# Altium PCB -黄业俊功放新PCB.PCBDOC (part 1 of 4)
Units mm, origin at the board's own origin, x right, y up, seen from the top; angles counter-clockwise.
Board outline 130 x 100.6 mm, 2 copper layers (Top Layer, Bottom Layer); 47 components, 24 nets, 117 pads, 4 vias.
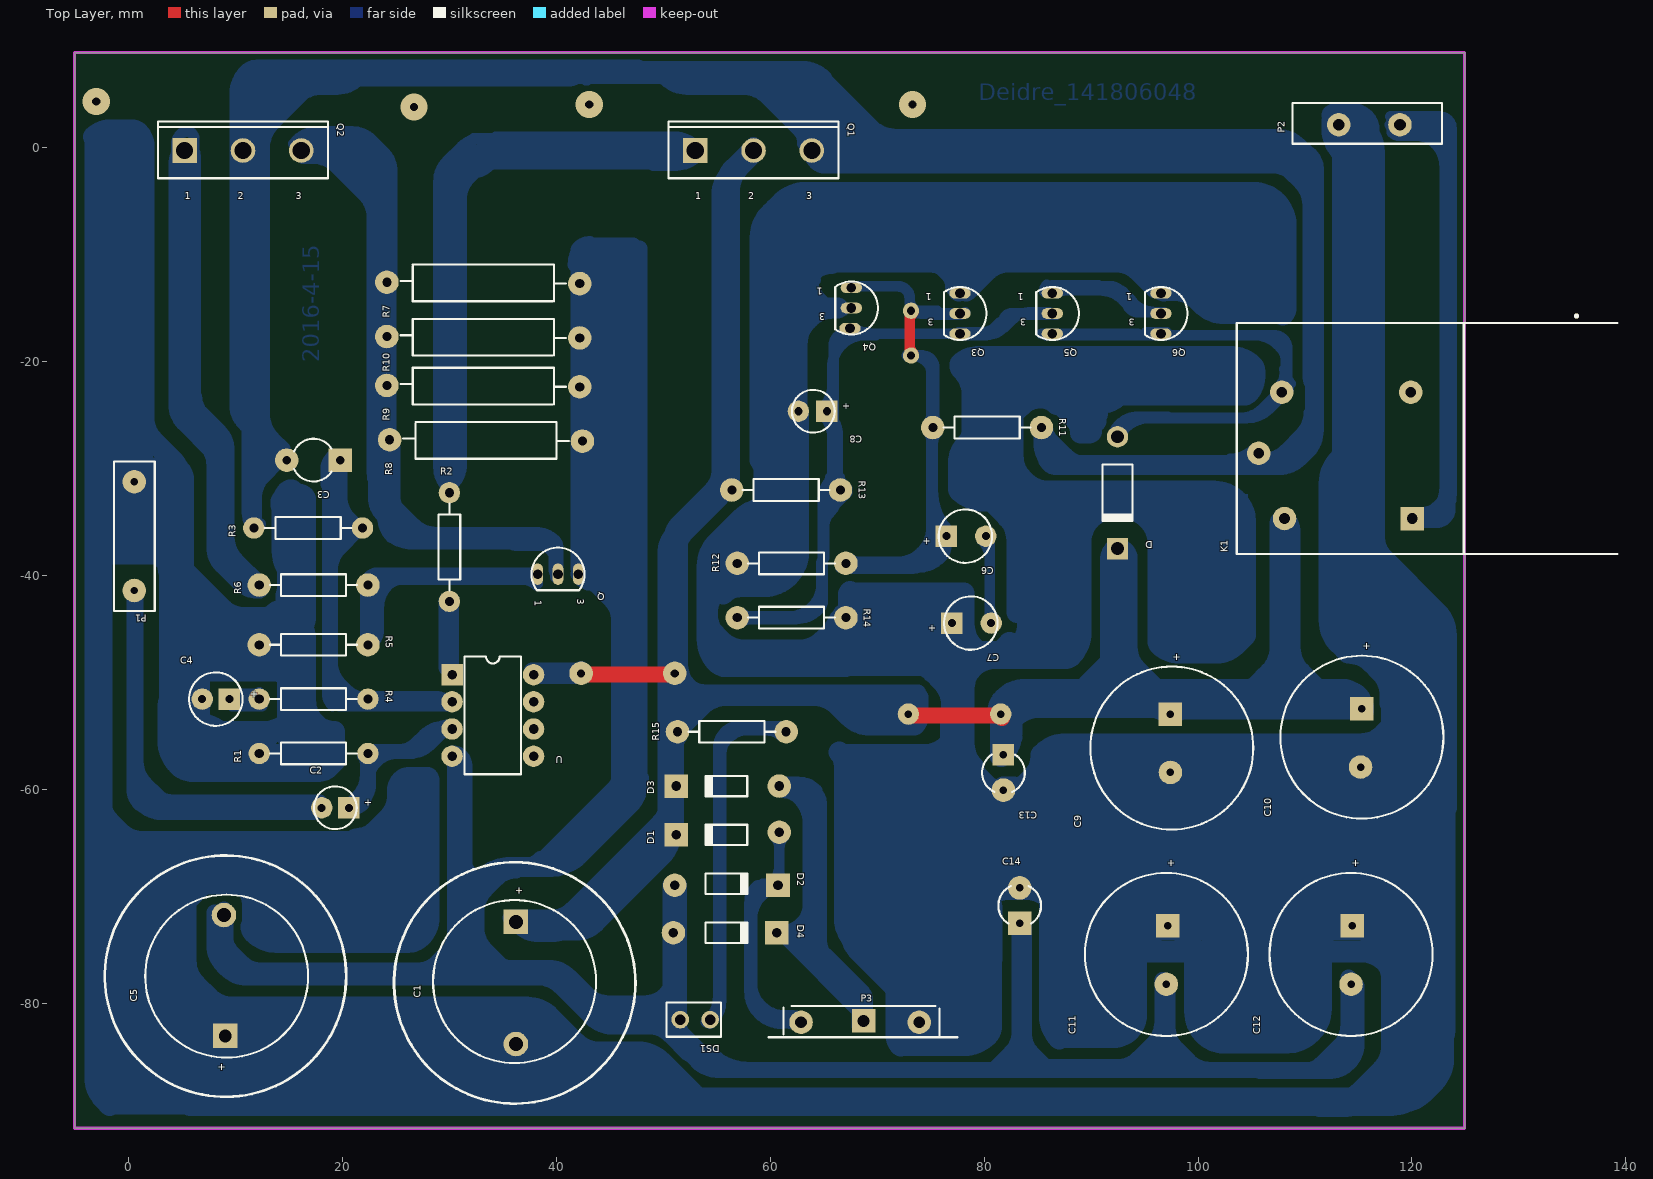
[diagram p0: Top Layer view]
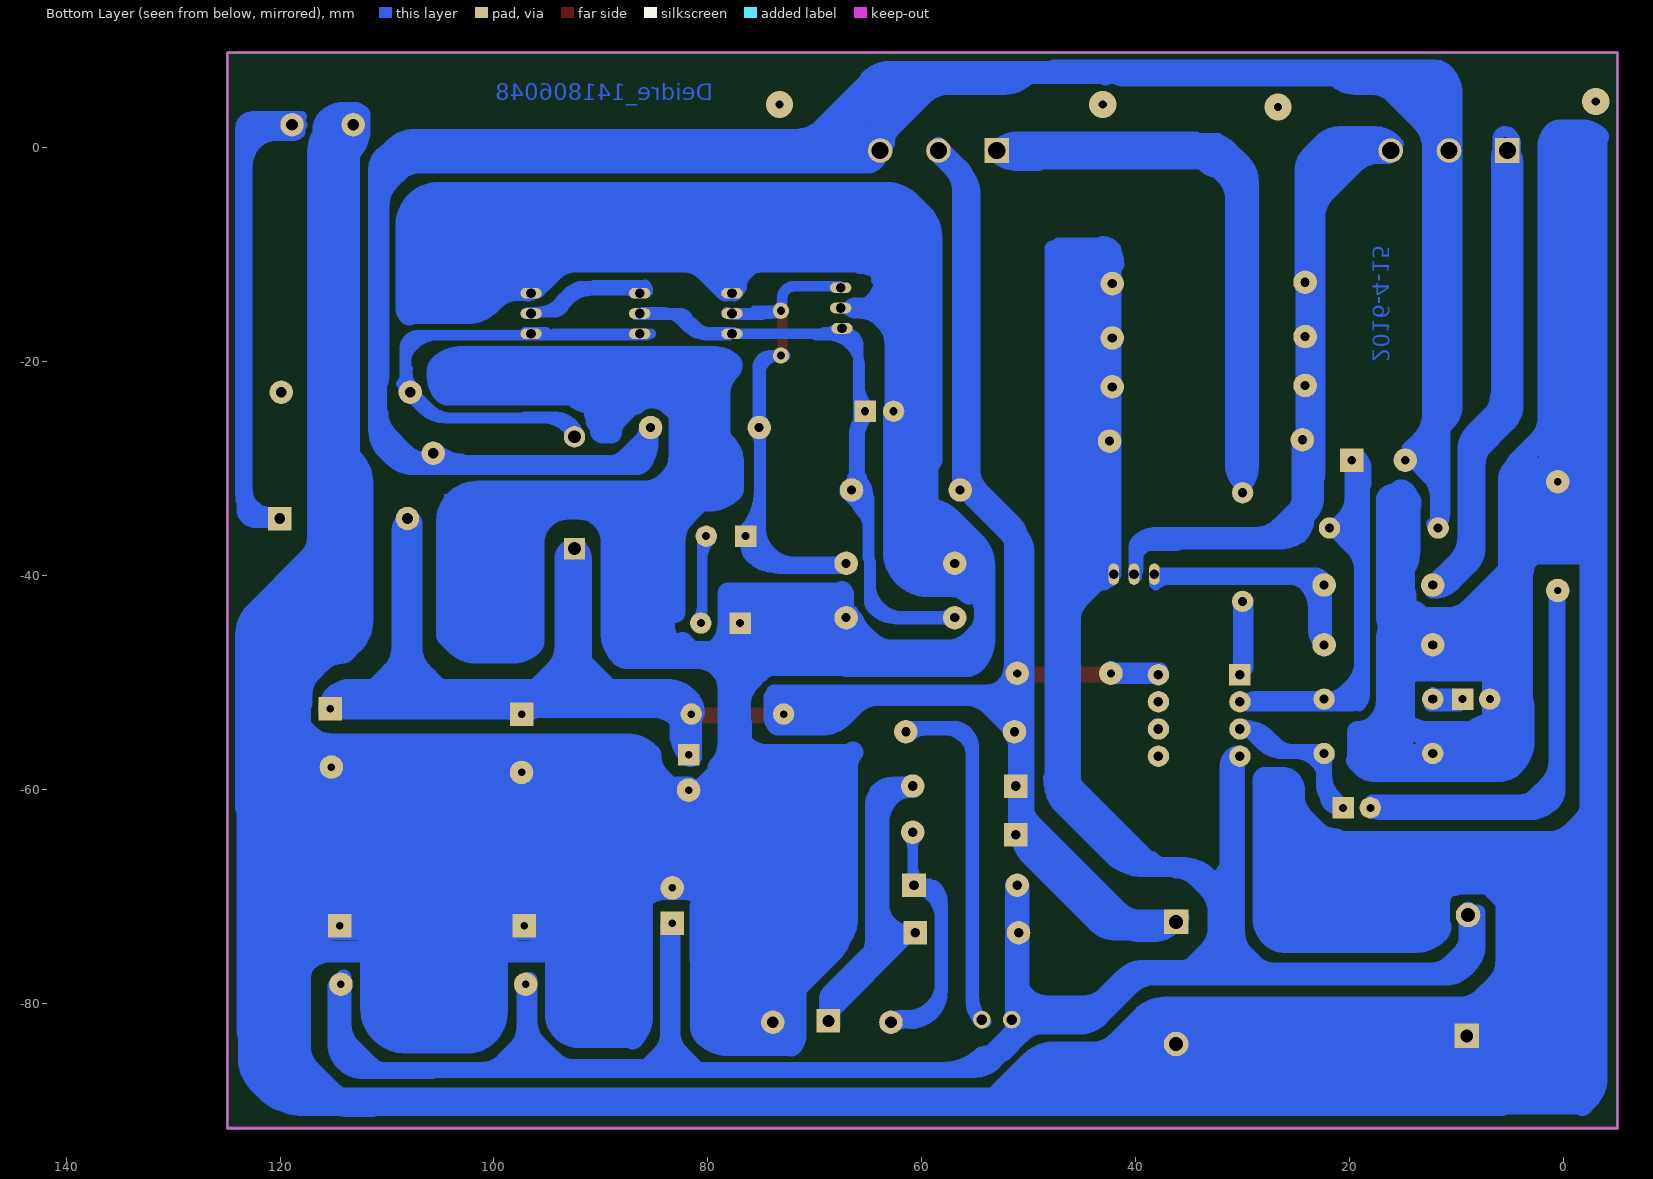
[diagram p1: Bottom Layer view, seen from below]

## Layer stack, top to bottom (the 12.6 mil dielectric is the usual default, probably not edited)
Top Layer: signal copper 0.0356
Dielectric: dielectric 0.32, FR-4, Dk 4.8
Bottom Layer: signal copper 0.0356

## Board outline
-5.08,-91.694 124.92,-91.694 124.92,8.906 -5.08,8.906

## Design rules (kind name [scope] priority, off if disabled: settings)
Clearance [All] p1: gap=0.5
ComponentClearance [All] p1: gap=0.254 collisioncheckmode=0
PolygonConnect [All] p1: connectstyle=Relief reliefconductorwidth=0.254 reliefentries=4 polygonreliefangle="90 Angle"
RoutingVias [All] p1: holewidth=0.6 width=1 viastyle="Through Hole" minholewidth=0.711 minwidth=1.27 maxholewidth=0.711 maxwidth=1.27
SolderMaskExpansion [All] p1: expansion=0.102
TestPointUsage [All] p1: valid=0 allowmultiple=FALSE
Testpoint [All] p1: side=15 testpointundercomponent=TRUE minsize=1.016 maxsize=2.54 preferedsize=1.524 minholesize=0 maxholesize=1.016 preferedholesize=0.813 testpointgrid=0.025 style=1023 order=1234567890
Width Width_3 [InNet('GND')] p1: maxlimit=14 minlimit=0.254 preferedwidth=2
Width Width_2 [InNet('+12V')] p2: maxlimit=5 minlimit=0.254 preferedwidth=1.5
Width Width_1 [InNet('-12V')] p3: maxlimit=4 minlimit=0.254 preferedwidth=1.5
Width [All] p4: maxlimit=2 minlimit=0.2 preferedwidth=1
17 further rules are at their usual default settings.

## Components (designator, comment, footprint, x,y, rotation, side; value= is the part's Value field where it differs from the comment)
C1 "Cap Pol1" RB7.6-15#1 36.068,-77.978 r90 top
C2 "Cap Pol1" CAPPR1.5-4x5#1 19.304,-61.722 r180 top
C3 "Cap" CAPR5-4X5#1 17.272,-29.21 r180 top
C4 "Cap Pol1" CAPPR2-5x6.8#1 8.128,-51.562 r180 top
C5 "Cap Pol1" RB7.6-15#2 9.144,-77.47 r270 top
C6 "Cap Pol1" CAPPR2-5x6.8#2 78.232,-36.322 r0 top (schematic designator C7)
C7 "Cap Pol1" CAPPR2-5x6.8#2 78.74,-44.45 r0 top
C8 "Cap Pol1" CAPPR1.5-4x5#2 64.008,-24.638 r180 top
C9 "Cap Pol1" RB7.6-15#3 97.536,-56.134 r90 top
C10 "Cap Pol1" RB7.6-15#4 115.316,-55.118 r90 top
C11 "Cap Pol1" RB7.6-15#5 97.028,-75.438 r90 top
C12 "Cap Pol1" RB7.6-15#5 114.3,-75.438 r90 top
C13 "Cap" CAPR5-4X5#2 81.788,-58.42 r270 top
C14 "Cap" CAPR5-4X5#3 83.312,-70.866 r90 top
D "1N4001" DIO10.46-5.3x2.8 92.456,-32.258 r270 top
D1 "Diode 1N914" DIO7.1-3.9x1.9#1 55.88,-64.262 r180 top
D2 "Diode 1N914" DIO7.1-3.9x1.9#2 55.88,-68.834 r0 top
D3 "Diode 1N914" DIO7.1-3.9x1.9#3 55.88,-59.69 r180 top
D4 "Diode 1N914" DIO7.1-3.9x1.9#3 55.88,-73.406 r0 top
DS1 "LED0" CAPR2.54-5.1x3.2 52.832,-81.534 r180 top
K1 "Relay-SPDT" DIP-P5/X1.65 121.412,-27.178 r180 top
P1 "Header 2" RAD-0.4#1 0.508,-36.322 r270 top
P2 "Header 2" RAD-0.4#2 115.824,2.286 r180 top
P3 "Header 3" HDR1X3 71.12,-81.788 r180 top
Q "BC547" BCY-W3/E4#1 40.132,-39.878 r270 top
Q1 "IRFPC50" TO-247AC 58.42,-0.254 r0 top
Q2 "IRFPC50" TO-247AC 10.668,-0.254 r0 top
Q3 "9014" BCY-W3/E4#1 77.724,-15.494 r180 top
Q4 "9014" BCY-W3/E4#2 67.564,-14.986 r180 top
Q5 "8050" BCY-W3/E4#1 86.36,-15.494 r180 top
Q6 "8050" BCY-W3/E4#1 96.52,-15.494 r180 top
R1 "Res2" AXIAL-0.4#1 17.272,-56.642 r180 top
R2 "Res2" AXIAL-0.4#1 29.972,-37.338 r90 top
R3 "Res2" AXIAL-0.4#1 16.764,-35.56 r180 top
R4 "Res2" AXIAL-0.4#1 17.272,-51.562 r0 top
R5 "Res2" AXIAL-0.4#2 17.272,-46.482 r0 top
R6 "Res2" AXIAL-0.4#2 17.272,-40.894 r180 top
R7 "Res2" AXIAL-0.4#3 33.528,-12.7 r180 top
R8 "Res2" AXIAL-0.4#3 33.782,-27.432 r180 top (schematic designator R7)
R9 "Res2" AXIAL-0.4#3 33.528,-22.352 r180 top (schematic designator R7)
R10 "Res2" AXIAL-0.4#3 33.528,-17.78 r180 top (schematic designator R7)
R11 "Res2" AXIAL-0.4#2 80.264,-26.162 r0 top
R12 "Res2" AXIAL-0.4#2 61.976,-38.862 r180 top
R13 "Res2" AXIAL-0.4#2 61.468,-32.004 r0 top
R14 "Res2" AXIAL-0.4#2 61.976,-43.942 r0 top
R15 "Res2" AXIAL-0.4#2 56.388,-54.61 r180 top
U "NE5532AP" P008 34.036,-53.086 r270 top

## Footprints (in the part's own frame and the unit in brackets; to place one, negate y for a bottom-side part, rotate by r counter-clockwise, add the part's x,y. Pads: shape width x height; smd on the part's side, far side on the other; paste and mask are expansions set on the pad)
AXIAL-0.4#1 [mm] "Resistor; 2 Leads"
  round 2 hole 0.85: 1(-5.08,0) 2(5.08,0)
  silkscreen extent -4.06,-1.02 4.06,1.02
AXIAL-0.4#2 [mm] "Resistor; 2 Leads"
  round 2.2 hole 0.85: 1(-5.08,0) 2(5.08,0)
  silkscreen extent -4.06,-1.02 4.06,1.02
AXIAL-0.4#3 [mm] "Resistor; 2 Leads"
  round 2.2 hole 0.85: 1(-8.636,0) 2(9.398,-0.127)
  silkscreen extent -7.37,-1.78 8.13,1.65
BCY-W3/E4#1 [mm] "TO, Flat Index; 3 In-Line, Axial Leads; Body Dia. 4.7mm"
  oval 2x1 hole 0.9: 1(0,-1.905) 2(0,0) 3(0,1.905)
  silkscreen extent -2.48,-2.48 1.5,2.48
BCY-W3/E4#2 [mm] "TO, Flat Index; 3 In-Line, Axial Leads; Body Dia. 4.7mm"
  oval 2x1 hole 0.9: 1(0,-1.905) 2(0,0) 3(0.127,1.905)
  silkscreen extent -2.48,-2.48 1.5,2.48
CAPPR1.5-4x5#1 [mm] "Capacitor, Electrolytic, Radial; Body 4 x 5 mm (Dia.xH typ); Pin Spacing 1.5 mm (typ)"
  rect 2x2 hole 0.75: 1(-1.27,0)
  round 2 hole 0.75: 2(1.27,0)
  silkscreen extent -2,-2 2,2
CAPPR1.5-4x5#2 [mm] "Capacitor, Electrolytic, Radial; Body 4 x 5 mm (Dia.xH typ); Pin Spacing 1.5 mm (typ)"
  rect 2x2 hole 0.75: 1(-1.27,0)
  round 2 hole 0.75: 2(1.397,0)
  silkscreen extent -2,-2 2,2
CAPPR2-5x6.8#1 [mm] "Capacitor, Electrolytic, Radial; Body 5 x 6.8 mm (Dia.xH typ); Pin Spacing 2 mm (typ)"
  rect 2x2 hole 0.75: 1(-1.27,0)
  round 2 hole 0.75: 2(1.27,0)
  silkscreen extent -2.5,-2.5 2.5,2.5
CAPPR2-5x6.8#2 [mm] "Capacitor, Electrolytic, Radial; Body 5 x 6.8 mm (Dia.xH typ); Pin Spacing 2 mm (typ)"
  rect 2x2 hole 0.75: 1(-1.778,0)
  round 2 hole 0.75: 2(1.905,0)
  silkscreen extent -2.5,-2.5 2.5,2.5
CAPR2.54-5.1x3.2 [mm] "Capacitor, Ceramic, Thru-Hole, Dipped Radial; Body 5.1 x 3.2 mm (WxT) Pin Spacing 2.54 mm (typ)"
  round 1.65 hole 1: 1(-1.524,0) 2(1.27,0)
  silkscreen extent -2.55,-1.6 2.55,1.6
CAPR5-4X5#1 [mm] "Capacitor; 2 Leads"
  rect 2.2x2.2 hole 0.8: 1(-2.5,0)
  round 2.2 hole 0.8: 2(2.5,0)
  silkscreen extent -1.69,-2 1.82,2
CAPR5-4X5#2 [mm] "Capacitor; 2 Leads"
  rect 2x2 hole 0.7: 1(-1.651,0)
  round 2.2 hole 0.7: 2(1.651,0)
  silkscreen extent -1.69,-2 1.82,2
CAPR5-4X5#3 [mm] "Capacitor; 2 Leads"
  rect 2.2x2.2 hole 0.7: 1(-1.651,0)
  round 2.2 hole 0.7: 2(1.651,0)
  silkscreen extent -1.69,-2 1.82,2
DIO7.1-3.9x1.9#1 [mm] "Diode, Axial; Body 3.8 x 1.9 mm (LxDia. max), Lead Dia. 0.53 mm (max)"
  round 2.2 hole 0.9: 1(-4.953,-0.254)
  rect 2.2x2.2 hole 0.9: 2(4.699,0)
  silkscreen extent -1.95,-0.95 2.05,0.95
DIO7.1-3.9x1.9#2 [mm] "Diode, Axial; Body 3.8 x 1.9 mm (LxDia. max), Lead Dia. 0.53 mm (max)"
  round 2.2 hole 0.9: 1(-4.826,-0.127)
  rect 2.2x2.2 hole 0.9: 2(4.826,-0.127)
  silkscreen extent -1.95,-0.95 2.05,0.95
DIO7.1-3.9x1.9#3 [mm] "Diode, Axial; Body 3.8 x 1.9 mm (LxDia. max), Lead Dia. 0.53 mm (max)"
  round 2.2 hole 0.9: 1(-4.953,0)
  rect 2.2x2.2 hole 0.9: 2(4.699,0)
  silkscreen extent -1.95,-0.95 2.05,0.95
DIO10.46-5.3x2.8 [mm] "Diode, Axial; Body 5.2 x 2.7 mm (LxDia. max), Lead Dia. 0.86 mm (max)"
  round 2 hole 1.2: 1(-5.23,0)
  rect 2x2 hole 1.2: 2(5.23,0)
  silkscreen extent -2.65,-1.4 2.75,1.4
DIP-P5/X1.65 [mm] "DIP; 5 Round Pins; Row Space 15.24 mm; Pitch 2.54 mm"
  rect 2.2x2.2 hole 1: 1(1.397,7.493)
  round 2.2 hole 1: 2(1.524,-4.318) 3(15.748,1.397) 4(13.335,7.493) 5(13.589,-4.318)
  silkscreen extent -17.8,-11.57 17.8,10.81
HDR1X3 [mm] "Connector; Header; 3 Position"
  rect 2.2x2.2 hole 1.1: 1(2.413,-0.127)
  round 2.2 hole 1.1: 2(-2.794,0) 3(8.255,0)
  silkscreen extent -6.35,-1.52 11.3,1.4
P008 [mm] "DIP; 8 Leads; Row Spacing 7.62 mm; Pitch 2.54 mm"
  rect 2x2 hole 0.9: 1(-3.81,-3.81)
  round 2 hole 0.9: 2(-1.27,-3.81) 3(1.27,-3.81) 4(3.81,-3.81) 5(3.81,3.81) 6(1.27,3.81) 7(-1.27,3.81) 8(-3.81,3.81)
  silkscreen extent -5.5,-2.65 5.5,2.65
RAD-0.4#1 [mm] "Servo Motor; 2 Leads"
  round 2.2 hole 0.7: 1(-5.08,0) 2(5.08,0)
  silkscreen extent -6.98,-1.91 6.98,1.91
RAD-0.4#2 [mm] "Servo Motor; 2 Leads"
  round 2.2 hole 1.1: 1(-3.048,0.127) 2(2.667,0.127)
  silkscreen extent -6.98,-1.91 6.98,1.91
RB7.6-15#1 [mm] "Polarized Capacitor (Radial); 2 Leads"
  rect 2.3x2.3 hole 1.3: 1(5.588,-0.127)
  round 2.3 hole 1.3: 2(-5.842,-0.127)
  silkscreen extent -7.62,-7.62 7.62,7.62
RB7.6-15#2 [mm] "Polarized Capacitor (Radial); 2 Leads"
  rect 2.3x2.3 hole 1.2: 1(5.588,-0.127)
  round 2.3 hole 1.3: 2(-5.715,-0.254)
  silkscreen extent -7.62,-7.62 7.62,7.62
RB7.6-15#3 [mm] "Polarized Capacitor (Radial); 2 Leads"
  rect 2.2x2.2 hole 0.7: 1(3.175,0.127)
  round 2.2 hole 0.7: 2(-2.286,0.127)
  silkscreen extent -7.62,-7.62 7.62,7.62
RB7.6-15#4 [mm] "Polarized Capacitor (Radial); 2 Leads"
  rect 2.2x2.2 hole 0.7: 1(2.667,0)
  round 2.2 hole 0.7: 2(-2.794,0.127)
  silkscreen extent -7.62,-7.62 7.62,7.62
RB7.6-15#5 [mm] "Polarized Capacitor (Radial); 2 Leads"
  rect 2.2x2.2 hole 0.7: 1(2.667,-0.127)
  round 2.2 hole 0.7: 2(-2.794,0)
  silkscreen extent -7.62,-7.62 7.62,7.62
TO-247AC [mm] "SIP with Mounting Hole; 3 Leads; Body 20 x 15.6 x 5 mm (typ); Pitch 5.45 mm"
  rect 2.3x2.3 hole 1.6: 1(-5.45,0)
  round 2.3 hole 1.6: 2(0,0) 3(5.45,0)
  silkscreen extent -7.95,-2.6 7.95,2.7

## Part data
C1 C2 C4 C5 C6 C7 C8 C9 C10 C11 C12: "Polarized Capacitor (Radial)"
C3 C13 C14: "Capacitor"
D: library part "Diode 1N4001", "1 Amp General Purpose Rectifier"
D1 D2 D3 D4: "High Conductance Fast Diode"
DS1: "Typical INFRARED GaAs LED"
K1: "Single-Pole Dual-Throw Relay"
P1 P2: "Header, 2-Pin"
P3: "Header, 3-Pin"
Q Q3 Q4 Q5 Q6: library part 2N3904, "NPN General Purpose Amplifier"
Q1 Q2: "HEXFET Power MOSFET"
R1 R2 R3 R4 R5 R6 R7 R8 R9 R10 R11 R12 R13 R14 R15: "Resistor"
U: "Dual Low-Noise Operational Amplifier"

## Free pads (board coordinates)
  round 2.2 hole 0.762: 0(42.291,-49.149) 1(51.054,-49.149)
  round 1.524 hole 0.762: 0(73.152,-15.24) 1(73.152,-19.431)
  round 2 hole 0.7: 4(81.534,-52.959) 5(72.898,-52.959)

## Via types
v1: diameter 2.54, hole 0.762, Top Layer to Bottom Layer, 4 vias

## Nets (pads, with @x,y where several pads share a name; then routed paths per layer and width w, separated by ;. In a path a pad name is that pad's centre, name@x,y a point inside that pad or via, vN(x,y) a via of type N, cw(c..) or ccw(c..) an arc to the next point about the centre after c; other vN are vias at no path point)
+12V: C1.1 C9.1 C10.1 C13.1 D1.2 D3.2 D.2 K1.4 pad.0@42.291,-49.149 pad.1@51.054,-49.149 pad.4 pad.5 Q1.2 R13.1 R15.2 U.8 | length 1051.8
  Top Layer w1.5: pad.0@42.291,-49.276 51.054,-49.276 ccw(c51.054,-49.149) pad.1@51.181,-49.149 ; pad.5@72.898,-53.086 81.048,-53.086 cw(c81.048,-53.953) pad.4@81.661,-53.34
  Bottom Layer w1.5: C1.1@35.687,-72.009 39.562,-72.009 ccw(c39.562,-69.407) 41.402,-71.247 49.629,-63.02 ccw(c47.721,-61.112) 50.419,-61.112 50.419,-60.96 ; C1.1@36.576,-72.009 37.183,-72.616 ccw(c39.091,-70.708) 39.091,-73.406 41.808,-73.406 ccw(c41.808,-70.708) 43.716,-72.616 50.01,-66.322 ccw(c48.102,-64.414) 50.8,-64.414 50.8,-63.246 50.8,-61.341 ; U.8@37.719,-49.403 41.783,-49.403 ccw(c41.783,-49.022) pad.0@42.164,-49.022 ; U.8@37.719,-48.895 41.984,-48.895 ccw(c41.984,-48.461) pad.0@42.291,-48.768 ; D1.2@50.165,-63.754 50.165,-37.948 cw(c52.863,-37.948) 50.955,-36.04 54.963,-32.032 ccw(c53.055,-30.124) 55.753,-30.124 55.753,-24.765 ; 50.673,-40.386 50.673,-36.932 cw(c53.371,-36.932) 51.463,-35.024 54.455,-32.032 ccw(c52.547,-30.124) 55.245,-30.124 55.245,-4.293 cw(c57.943,-4.293) 56.035,-2.385 Q1.2@58.293,-0.127 ; 50.8,-61.976 cw(c50.493,-62.283) 50.927,-62.283 50.927,-62.382 cw(c48.229,-62.382) 50.137,-64.29 42.7,-71.727 cw(c40.792,-69.819) 40.792,-72.517 35.941,-72.517 cw(c35.941,-73.13) 36.375,-72.697 36.421,-72.743 ccw(c38.329,-70.835) 38.329,-73.533 39.522,-73.533 ccw(c39.522,-70.835) 41.43,-72.743 50.239,-63.934 ccw(c49.806,-63.5) 50.419,-63.5 50.419,-56.109 cw(c53.117,-56.109) 51.209,-54.201 52.832,-52.578 ; 50.8,-58.166 50.8,-38.329 ; 50.8,-39.497 50.8,-38.202 cw(c53.498,-38.202) 51.59,-36.294 55.88,-32.004 cw(c56.493,-31.391) 55.626,-31.391 55.626,-3.658 cw(c58.324,-3.658) 56.416,-1.75 Q1.2@58.42,0.254 ; 50.912,-60.89 ccw(c48.483,-59.715) D3.2@51.181,-59.715 ; D3.2@50.927,-60.604 D3.2@50.927,-59.563 ; R15.2@50.927,-54.61 50.927,-54.356 cw(c53.993,-54.356) 51.181,-53.134 cw(c53.993,-54.356) 51.308,-52.876 cw(c53.993,-54.356) 51.562,-52.488 cw(c53.993,-54.356) 51.825,-52.188 cw(c53.03,-53.393) 53.03,-51.689 54.229,-51.689 ; 50.927,-47.625 50.927,-38.202 cw(c53.625,-38.202) 51.717,-36.294 54.963,-33.048 ccw(c53.055,-31.14) 55.753,-31.14 55.753,-28.321 ; R15.2@51.061,-54.363 ccw(c49.85,-53.152) 51.562,-53.152 ; D1.2@51.181,-64.135 R15.2@51.181,-54.61 ; R15.2@51.181,-54.483 51.181,-38.608 ; R15.2@51.181,-54.229 ccw(c49.341,-52.389) 51.308,-54.093 ccw(c49.341,-52.389) R15.2@51.561,-53.747 ; 51.181,-53.458 ccw(c52.46,-53.458) R15.2@51.555,-54.363 ; R15.2@51.308,-54.483 ccw(c51.308,-54.61) R15.2@51.292,-54.484 ; 51.308,-38.227 51.308,-37.948 cw(c54.006,-37.948) 52.098,-36.04 55.09,-33.048 ccw(c53.182,-31.14) 55.88,-31.14 55.88,-27.94 ; R15.2@51.435,-55.118 cw(c52.661,-55.118) 51.794,-54.251 53.712,-52.333 cw(c55.88,-54.501) 55.88,-51.435 ; 51.435,-50.673 ccw(c52.048,-50.06) 51.562,-50.778 ccw(c52.048,-50.06) 52.048,-50.927 73.787,-50.927 ; 51.435,-47.625 51.435,-48.133 ccw(c54.501,-48.133) 51.562,-49.006 ccw(c54.501,-48.133) 52.333,-50.301 52.442,-50.41 ccw(c54.61,-48.242) 53.13,-50.927 ccw(c54.61,-48.242) 54.61,-51.308 ; pad.1@51.562,-48.412 ccw(c54.26,-48.412) 52.352,-50.32 ccw(c53.817,-48.855) 52.353,-50.321 ccw(c53.817,-48.855) 53.817,-50.927 ; 51.562,-35.814 51.562,-53.69 cw(c50.261,-53.69) R15.2@51.561,-53.747 ; 54.69,-51.435 ccw(c54.69,-51.627) 54.554,-51.491 cw(c52.386,-49.323) 52.386,-52.389 51.943,-52.389 cw(c49.341,-52.389) R15.2@51.561,-53.747 ; 55.372,-51.435 72.21,-51.435 cw(c72.21,-51.869) 72.517,-51.562 ; R13.1@56.388,-31.645 56.388,-4.064 cw(c59.454,-4.064) 57.286,-1.896 Q1.2@58.674,-0.508 ; 64.008,-51.435 cw(c64.008,-54.501) 66.176,-52.333 67.174,-53.331 ccw(c69.342,-51.163) 69.342,-54.229 ccw(c69.342,-49.56) pad.5@72.717,-52.786 ; 67.31,-52.324 ccw(c69.15,-50.484) 67.605,-52.578 ccw(c69.15,-50.484) 69.15,-53.086 71.86,-53.086 ccw(c71.86,-53.064) 71.876,-53.08 ccw(c70.358,-54.597) 70.358,-52.451 ccw(c70.358,-49.385) 72.517,-51.562 ; 67.564,-52.578 68.856,-52.578 ccw(c68.856,-51.711) 69.469,-52.324 ; 67.945,-53.594 68.221,-53.594 cw(c68.221,-54.461) 68.834,-53.848 ; 68.615,-51.435 cw(c68.615,-57.242) pad.5@72.721,-53.136 ; 69.215,-54.229 73.353,-54.229 ccw(c73.353,-53.795) 73.66,-54.102 ccw(c72.74,-53.182) 74.041,-53.182 74.041,-51.488 ; 69.228,-54.229 ccw(c69.228,-49.289) pad.5@72.721,-52.782 ; 71.501,-51.308 73.607,-51.308 ccw(c73.607,-50.874) 73.914,-51.181 cw(c73.607,-51.488) 74.041,-51.488 ; 71.829,-54.229 ccw(c71.829,-53.795) 72.136,-54.102 ccw(c70.91,-52.876) 72.644,-52.876 72.644,-51.435 72.526,-51.553 cw(c70.358,-49.385) 72.517,-51.562 ; 72.644,-51.742 ccw(c74.115,-51.742) pad.5@73.075,-52.782 ; pad.5@72.884,-52.709 ccw(c72.817,-51.488) 74.041,-51.488 ; pad.4@81.026,-52.841 cw(c83.194,-52.841) 81.661,-51.308 cw(c83.807,-53.454) 83.807,-50.419 113.634,-50.419 cw(c113.634,-51.72) 114.554,-50.8 ccw(c114.861,-51.107) 114.427,-51.107 ; C13.1@81.28,-57.023 81.28,-54.037 ; 81.28,-55.193 ccw(c83.618,-55.193) C13.1@81.965,-56.846 ; 81.28,-54.176 cw(c82.751,-54.176) pad.4@81.711,-53.136 ; 81.28,-54.066 cw(c82.498,-54.066) pad.4@81.698,-53.148 ; pad.4@81.447,-53.193 cw(c80.724,-55.144) 82.804,-55.144 ; C13.1@81.534,-57.15 ccw(c81.534,-56.843) 81.751,-57.06 81.906,-56.905 ccw(c79.738,-54.737) 82.804,-54.737 82.804,-52.832 ; C13.1@81.661,-57.15 81.661,-54.439 ccw(c79.927,-54.439) 81.153,-53.213 81.906,-52.46 cw(c84.074,-54.628) 84.074,-51.562 87.757,-51.562 ; 81.915,-55.499 cw(c84.981,-55.499) 82.813,-53.331 ; 81.915,-55.294 cw(c84.486,-55.294) 82.668,-53.476 ; 81.915,-54.786 cw(c84.486,-54.786) 82.668,-52.968 cw(c84.836,-55.136) 84.836,-52.07 90.043,-52.07 ; 82.296,-54.987 cw(c84.433,-54.987) 82.922,-53.476 cw(c85.09,-55.644) 85.09,-52.578 85.344,-52.578 ccw(c85.344,-49.512) 87.512,-51.68 87.621,-51.571 cw(c89.789,-53.739) 89.789,-50.673 114.142,-50.673 cw(c114.142,-51.974) 115.062,-51.054 cw(c113.529,-52.587) 115.697,-52.587 C10.1@115.697,-52.705 ; 83.185,-51.816 97.409,-51.816 ; 83.365,-51.816 111.252,-51.816 ccw(c111.252,-48.75) 113.42,-50.918 ; 84.836,-52.578 99.441,-52.578 ; 85.852,-51.562 112.259,-51.562 ; 88.414,-51.689 ccw(c88.414,-50.822) 89.027,-51.435 89.154,-51.435 ccw(c89.154,-50.822) 89.588,-51.255 91.685,-49.158 ccw(c89.517,-46.99) 92.583,-46.99 92.583,-45.212 92.583,-46.736 ccw(c95.649,-46.736) 93.481,-48.904 95.114,-50.537 ccw(c97.282,-48.369) 97.282,-51.435 101.473,-51.435 ccw(c101.473,-56.428) C9.1@97.675,-53.186 ; 89.535,-50.038 91.558,-48.015 ccw(c89.39,-45.847) 92.456,-45.847 D.2@92.456,-37.465 ; 91.567,-47.498 91.567,-38.564 cw(c93.301,-38.564) 92.075,-37.338 ccw(c92.382,-37.031) 92.382,-37.465 92.911,-37.465 cw(c92.911,-37.899) 93.218,-37.592 ccw(c93.525,-37.899) 93.091,-37.899 93.091,-49.171 ccw(c93.958,-49.171) 93.345,-49.784 ; 91.567,-40.238 cw(c95.206,-40.238) D.2@92.633,-37.665 ; 91.567,-38.884 cw(c92.742,-38.884) D.2@92.506,-37.733 ; D.2@92.279,-37.665 cw(c90.319,-39.625) 93.091,-39.625 ; 93.191,-51.562 cw(c93.191,-57.177) C9.1@97.162,-53.206 ; 93.98,-52.324 93.481,-51.825 cw(c95.649,-49.657) 92.583,-49.657 D.2@92.583,-37.338 ; 95.644,-52.578 cw(c95.644,-54.724) C9.1@97.162,-53.206 ; 96.093,-50.627 cw(c93.761,-52.959) C9.1@97.059,-52.959 ; 96.266,-50.8 cw(c94.332,-52.734) C9.1@97.06,-52.933 ; 96.266,-50.546 94.389,-48.669 cw(c96.297,-46.761) 93.599,-46.761 93.599,-38.49 ccw(c92.351,-38.49) 93.233,-37.607 ccw(c92.583,-38.258) D.2@92.583,-37.338 ; C9.1@96.596,-52.146 cw(c96.779,-52.329) C9.1@96.779,-52.07 ; 96.774,-51.308 93.481,-48.015 cw(c95.649,-45.847) 92.583,-45.847 D.2@92.583,-37.338 ; C9.1@97.028,-52.07 112.014,-52.07 ; C9.1@97.536,-52.705 C10.1@115.189,-52.705 ; C9.1@97.656,-52.698 cw(c99.174,-54.216) 99.174,-52.07 ; 99.174,-52.578 ccw(c99.174,-54.724) C9.1@97.656,-53.206 ; 100.4,-52.07 ccw(c100.4,-55.95) C9.1@97.656,-53.206 ; 101.013,-51.816 ccw(c101.013,-56.563) C9.1@97.656,-53.206 ; 101.627,-51.562 ccw(c101.627,-57.177) C9.1@97.656,-53.206 ; 103.632,-51.943 cw(c103.939,-51.943) 103.722,-51.726 106.925,-48.523 ccw(c104.757,-46.355) 107.823,-46.355 K1.4@107.823,-34.544 ; 103.632,-51.689 ccw(c103.632,-48.623) 105.8,-50.791 107.052,-49.539 ccw(c104.884,-47.371) 107.95,-47.371 107.95,-40.132 ; 105.918,-49.53 106.544,-48.904 ccw(c104.376,-46.736) 107.442,-46.736 107.442,-35.105 cw(c107.876,-35.105) 107.569,-34.798 cw(c108.182,-35.411) 108.182,-34.544 108.316,-34.677 cw(c107.052,-35.941) 108.839,-35.941 108.839,-46.736 ccw(c111.905,-46.736) 109.737,-48.904 110.617,-49.784 ; 107.442,-37.049 cw(c110.455,-37.049) K1.4@108.324,-34.918 ; K1.4@107.823,-34.417 107.823,-51.658 ccw(c109.124,-51.658) 108.204,-52.578 ; K1.4@107.83,-34.918 cw(c105.392,-37.356) 108.839,-37.356 ; 107.95,-45.593 107.95,-47.117 ccw(c111.016,-47.117) 108.848,-49.285 111.506,-51.943 ; 107.95,-35.823 cw(c109.229,-35.823) K1.4@108.324,-34.918 ; K1.4@107.95,-34.671 107.95,-45.847 ccw(c111.016,-45.847) 108.848,-48.015 ; K1.4@107.979,-35.007 cw(c107.647,-36.152) 108.839,-36.152 ; K1.4@108.077,-34.671 108.077,-45.974 ccw(c111.143,-45.974) 108.975,-48.142 113.157,-52.324 ; 109.855,-51.435 110.744,-51.435 ccw(c110.744,-48.369) 112.912,-50.537 ; 110.179,-50.673 cw(c110.179,-57.588) C10.1@115.069,-52.698 ; 113.665,-51.435 ccw(c113.972,-51.435) 113.755,-51.652 ; 113.858,-52.705 ccw(c113.858,-50.993) C10.1@115.069,-52.204 ; C10.1@114.427,-52.324 114.427,-51.107 ; C10.1@115.345,-52.102 cw(c115.426,-51.107) 114.427,-51.107 ; 51.181,-55.762 cw(c52.46,-55.762) R15.2@51.555,-54.857 ; 51.181,-55.762 cw(c52.46,-55.762) R15.2@51.555,-54.857 ; 51.181,-55.762 cw(c52.46,-55.762) R15.2@51.555,-54.857 ; 51.181,-55.762 cw(c52.46,-55.762) R15.2@51.555,-54.857 ; 51.181,-55.762 cw(c52.46,-55.762) R15.2@51.555,-54.857 ; R15.2@51.181,-54.61 ccw(c50.261,-53.69) R15.2@51.292,-54.484 ; R15.2@51.181,-54.61 cw(c51.308,-54.61) R15.2@51.292,-54.484 ; R15.2@51.292,-54.484 ccw(c50.261,-53.69) 51.308,-54.462 ccw(c50.261,-53.69) R15.2@51.561,-53.747 ; 95.031,-51.816 cw(c95.031,-54.829) C9.1@97.162,-52.698 ; 95.031,-51.816 cw(c95.031,-54.829) C9.1@97.162,-52.698 ; 95.031,-51.816 cw(c95.031,-54.829) C9.1@97.162,-52.698 ; 95.031,-51.816 cw(c95.031,-54.829) C9.1@97.162,-52.698 ; 95.951,-52.197 cw(c95.951,-53.909) C9.1@97.162,-52.698 ; 95.951,-52.197 cw(c95.951,-53.909) C9.1@97.162,-52.698 ; 95.951,-52.197 cw(c95.951,-53.909) C9.1@97.162,-52.698 ; C9.1@97.162,-53.206 ccw(c93.805,-56.563) 93.805,-51.816 cw(c93.805,-56.563) C9.1@97.162,-53.206 ; C9.1@97.656,-53.206 cw(c98.867,-54.417) 98.867,-52.705 ; C9.1@97.656,-52.204 ccw(c98.867,-50.993) 98.867,-52.705 ; C9.1@97.656,-52.204 ccw(c98.561,-51.299) 98.561,-52.578 ; C9.1@97.656,-52.204 ccw(c98.561,-51.299) 98.561,-52.578 ; C9.1@97.656,-52.204 ccw(c98.867,-50.993) 98.867,-52.705 ; C9.1@97.656,-52.204 ccw(c98.867,-50.993) 98.867,-52.705 ; C9.1@97.656,-52.204 ccw(c98.561,-51.299) 98.561,-52.578 ; C9.1@97.656,-52.204 ccw(c98.867,-50.993) 98.867,-52.705 ; K1.4@108.324,-34.918 ccw(c109.535,-36.129) 107.823,-36.129 cw(c109.535,-36.129) K1.4@108.324,-34.918 ; C10.1@115.189,-52.705 ccw(c115.189,-52.324) C10.1@115.57,-52.324 ; C10.1@115.189,-52.705 ccw(c115.189,-52.324) C10.1@115.57,-52.324 ; C10.1@115.189,-52.705 ccw(c115.189,-52.324) C10.1@115.57,-52.324 ; 115.189,-51.299 ccw(c116.468,-51.299) C10.1@115.563,-52.204 ; 115.189,-51.299 ccw(c116.468,-51.299) C10.1@115.563,-52.204 ; 115.189,-51.299 ccw(c116.468,-51.299) C10.1@115.563,-52.204 ; 115.189,-51.299 ccw(c116.468,-51.299) C10.1@115.563,-52.204
+18V: 
-12V: C5.2 C11.2 C12.2 C14.1 D2.1 D4.1 DS1.2 Q.3 R7.1 R8.1 R9.1 R10.1 U.4 | length 1048.9
  Bottom Layer w1.5: C5.2@8.001,-71.501 8.001,-74.574 ccw(c10.699,-74.574) 8.791,-76.482 9.116,-76.807 ccw(c11.024,-74.899) 11.024,-77.597 38.379,-77.597 cw(c38.379,-80.295) 40.287,-78.387 43.279,-81.379 ccw(c45.187,-79.471) 45.187,-82.169 48.666,-82.169 cw(c48.666,-84.867) 50.574,-82.959 52.324,-84.709 54,-84.709 ; C5.2@8.636,-71.755 8.636,-73.939 ccw(c11.334,-73.939) 9.426,-75.847 10.005,-76.426 ccw(c11.913,-74.518) 11.913,-77.216 39.014,-77.216 cw(c39.014,-79.914) 40.922,-78.006 43.66,-80.744 ccw(c45.568,-78.836) 45.568,-81.534 DS1.2@51.562,-81.534 ; C5.2@8.89,-71.247 8.89,-73.431 ccw(c11.588,-73.431) 9.68,-75.339 10.513,-76.172 ccw(c12.421,-74.264) 12.421,-76.962 18.288,-76.962 ; C5.2@9.017,-71.628 9.017,-73.812 ccw(c11.715,-73.812) 9.807,-75.72 10.259,-76.172 ccw(c12.167,-74.264) 12.167,-76.962 26.949,-76.962 ccw(c26.949,-74.264) 28.857,-76.172 29.69,-75.339 ccw(c27.782,-73.431) 30.48,-73.431 U.4@30.48,-57.404 ; 28.6,-77.216 ccw(c28.6,-74.518) 30.508,-76.426 31.341,-75.593 ccw(c29.433,-73.685) 31.369,-75.565 31.369,-57.76 ccw(c30.251,-57.76) 30.251,-56.642 U.4@30.226,-56.642 ; 31.115,-63.246 31.115,-66.065 ccw(c33.813,-66.065) 31.905,-67.973 ; 31.242,-66.294 ccw(c33.695,-66.294) 31.96,-68.028 32.639,-68.707 33.318,-68.028 cw(c35.052,-69.763) 35.052,-67.31 ; 31.369,-70.231 33.754,-67.846 cw(c35.662,-69.754) 35.662,-67.056 39.141,-67.056 ccw(c39.141,-64.358) 41.049,-66.266 46.454,-60.861 ccw(c44.546,-58.953) 47.244,-58.953 47.244,-10.149 ; 31.369,-69.85 33.246,-67.973 cw(c35.154,-69.881) 35.154,-67.183 37.617,-67.183 ccw(c37.617,-64.485) 39.525,-66.393 46.073,-59.845 ccw(c44.165,-57.937) 46.863,-57.937 46.863,-43.282 ccw(c44.165,-43.282) 46.073,-41.374 44.859,-40.16 ccw(c42.951,-42.068) 42.951,-39.37 Q.3@42.037,-39.37 ; 31.623,-70.104 31.623,-73.685 ccw(c34.321,-73.685) 32.413,-75.593 33.655,-76.835 ; 32.385,-74.422 33.881,-75.918 ccw(c35.789,-74.01) 35.789,-76.708 39.268,-76.708 cw(c39.268,-79.406) 41.176,-77.498 42.898,-79.22 ccw(c44.806,-77.312) 44.806,-80.01 48.285,-80.01 ccw(c48.285,-77.312) 50.193,-79.22 50.388,-79.025 ccw(c49.087,-77.724) 50.927,-77.724 ; 35.535,-67.437 ccw(c35.535,-70.135) 33.627,-68.227 32.751,-69.103 ; 35.56,-67.437 39.522,-67.437 ccw(c39.522,-64.739) 40.34,-67.31 ccw(c39.522,-64.739) 40.834,-67.097 ccw(c40.157,-64.485) 42.065,-66.393 46.962,-61.496 ccw(c45.054,-59.588) 47.698,-60.125 47.752,-60.071 cw(c48.059,-59.764) 47.716,-60.03 ; 35.56,-67.31 36.601,-67.31 ccw(c36.601,-64.612) 38.509,-66.52 ; 35.56,-67.183 ccw(c35.56,-69.636) 33.826,-67.901 33.175,-68.552 ccw(c35.083,-70.46) 32.751,-69.103 ; 35.814,-67.31 36.855,-67.31 ccw(c36.855,-64.612) 38.763,-66.52 45.311,-59.972 ccw(c43.403,-58.064) 46.101,-58.064 46.101,-43.663 ccw(c43.403,-43.663) 45.311,-41.755 44.732,-41.176 ccw(c42.824,-43.084) 42.824,-40.386 Q.3@42.418,-40.386 ; 36.195,-67.564 ccw(c36.195,-70.017) 34.461,-68.282 33.302,-69.441 ccw(c35.21,-71.349) 32.512,-71.349 32.512,-73.05 ccw(c35.21,-73.05) 33.302,-74.958 35.024,-76.68 ccw(c36.932,-74.772) 36.932,-77.47 39.751,-77.47 ; 39.116,-76.835 36.17,-76.835 cw(c36.17,-74.137) 35.352,-76.708 cw(c36.17,-74.137) 34.262,-76.045 33.175,-74.958 cw(c35.083,-73.05) 32.385,-73.05 32.385,-70.46 cw(c35.083,-70.46) 32.751,-69.103 ; 41.783,-10.922 cw(c44.236,-10.922) 42.501,-9.188 cw(c42.607,-9.293) 42.607,-9.144 47.139,-9.144 ; Q.3@42.037,-39.878 45.466,-39.878 ccw(c45.466,-39.571) 45.683,-39.788 ; Q.3@42.037,-39.116 42.037,-9.705 cw(c42.471,-9.705) 42.164,-9.398 cw(c43.084,-10.318) 43.084,-9.017 ; 42.291,-16.256 46.863,-16.256 ; R8.1@42.418,-27.432 R8.1@43.459,-27.432 ; 42.545,-39.878 44.475,-39.878 cw(c44.475,-42.576) 46.383,-40.668 47.498,-41.783 ; R8.1@42.545,-27.559 47.117,-27.559 ; R8.1@42.545,-27.432 43.586,-27.432 cw(c43.586,-30.13) 45.494,-28.222 46.594,-29.322 cw(c45.943,-29.972) 46.863,-29.972 46.863,-30.681 ccw(c47.297,-30.681) 46.99,-30.988 46.99,-35.966 cw(c44.292,-35.966) 46.2,-37.874 45.085,-38.989 ; 42.672,-21.082 44.729,-21.082 ccw(c44.729,-18.384) 46.637,-20.292 ccw(c45.172,-18.827) 47.244,-18.827 47.244,-17.628 ccw(c44.546,-17.628) 46.454,-15.72 ; 42.926,-40.64 cw(c42.926,-41.866) 43.793,-40.999 45.057,-42.263 cw(c43.149,-44.171) 45.847,-44.171 45.847,-59.501 cw(c43.245,-59.501) 45.085,-61.341 ; 42.926,-39.37 43.459,-39.37 ccw(c43.459,-36.672) 45.367,-38.58 47.244,-36.703 47.244,-35.994 cw(c47.678,-35.994) 47.371,-35.687 ; 43.053,-16.51 44.221,-16.51 ccw(c44.221,-13.812) 46.129,-15.72 46.631,-15.218 ccw(c45.15,-13.738) 47.244,-13.738 ccw(c44.739,-13.738) 46.51,-11.966 ccw(c44.602,-13.874) 44.602,-11.176 42.904,-11.176 ccw(c42.904,-12.043) 42.291,-11.43 ccw(c41.678,-10.817) 42.545,-10.817 42.545,-10.795 cw(c42.852,-10.795) 42.635,-10.578 42.799,-10.414 46.215,-10.414 ; 43.126,-80.21 ccw(c43.663,-77.566) 43.663,-80.264 48.031,-80.264 ccw(c48.031,-77.566) 49.939,-79.474 50.137,-79.276 ccw(c48.229,-77.368) 50.673,-78.511 ccw(c48.229,-77.368) 50.756,-78.314 cw(c48.483,-76.86) 50.673,-78.436 D2.1@50.673,-68.961 ; 43.307,-10.795 43.307,-38.862 cw(c43.92,-38.862) 43.487,-38.428 45.308,-36.607 ccw(c44.007,-35.306) 45.847,-35.306 45.847,-33.528 ccw(c45.54,-33.221) 45.974,-33.221 45.974,-13.818 ccw(c43.276,-13.818) 45.184,-11.91 cw(c44.502,-11.228) 44.502,-12.192 44.502,-35.604 cw(c42.589,-35.604) 43.942,-36.957 ; 43.332,-21.209 cw(c43.332,-23.907) 44.715,-21.59 47.244,-21.59 ; 43.434,-16.51 44.602,-16.51 cw(c44.602,-19.208) 46.51,-17.3 47.244,-18.034 47.244,-12.421 ; R8.1@43.459,-27.305 ccw(c43.459,-24.607) 44.365,-27.149 ccw(c43.967,-24.48) 45.875,-26.388 46.216,-26.047 ccw(c44.655,-24.486) 46.832,-24.854 ccw(c44.655,-24.486) 46.863,-24.486 ccw(c44.165,-24.486) 46.736,-23.668 46.736,-23.495 46.532,-23.291 ccw(c44.222,-24.282) 46.001,-22.506 ; 44.45,-35.687 44.45,-15.85 cw(c47.148,-15.85) 45.24,-13.942 45.847,-13.335 ccw(c45.234,-12.722) 46.101,-12.722 46.101,-10.668 ; 45.339,-21.59 ccw(c45.952,-21.59) 45.519,-22.024 46,-22.505 ; 45.692,-39.779 ccw(c43.784,-37.871) 46.48,-37.975 ccw(c44.546,-36.093) 47.244,-36.093 ; 45.974,-26.924 46.482,-26.416 ; 46.101,-61.849 47.089,-60.861 ccw(c45.181,-58.953) 47.879,-58.953 ; 47.371,-80.518 50.187,-80.518 ccw(c50.187,-79.651) 50.8,-80.264 ; 47.625,-11.532 47.625,-59.764 ccw(c48.059,-59.764) 47.716,-60.03 ; 47.752,-59.69 47.752,-9.398 ; 47.752,-59.588 cw(c45.054,-59.588) 47.716,-60.03 ; D4.1@50.68,-73.653 cw(c48.856,-75.477) 51.435,-75.477 ; DS1.2@51.181,-81.153 51.181,-81.432 ccw(c53.879,-81.432) 51.971,-83.34 53.058,-84.427 ccw(c54.966,-82.519) 54.966,-85.217 ; 51.181,-80.391 51.181,-81.178 ccw(c53.879,-81.178) 51.971,-83.086 54.328,-85.443 ccw(c56.236,-83.535) 56.236,-86.233 ; D2.1@51.435,-68.961 51.435,-82.575 ccw(c54.133,-82.575) 52.225,-84.483 53.185,-85.443 ccw(c55.093,-83.535) 55.093,-86.233 ; 54.409,-84.783 ccw(c57.91,-81.282) 57.91,-86.233 ; 54.991,-86.233 109.753,-86.233 ; 81.026,-86.106 82.522,-84.61 ccw(c80.614,-82.702) 83.312,-82.702 C14.1@83.312,-72.39 ; 82.296,-85.217 cw(c82.296,-86.443) 83.163,-85.576 83.312,-85.725 ; C14.1@83.312,-72.517 83.312,-83.464 ccw(c86.01,-83.464) 84.102,-85.372 84.836,-86.106 ; C14.1@83.693,-72.644 83.693,-82.829 ccw(c86.391,-82.829) 84.483,-84.737 85.725,-85.979 86.106,-85.979 ; 84.455,-85.979 92.481,-85.979 ccw(c92.481,-83.281) 94.389,-85.189 95.857,-83.721 ccw(c93.949,-81.813) 96.647,-81.813 C11.2@96.647,-77.851 ; 94.488,-86.233 95.984,-84.737 ccw(c94.076,-82.829) 96.774,-82.829 C11.2@96.774,-78.105 ; 96.111,-85.626 ccw(c94.203,-83.718) 96.901,-83.718 C11.2@96.901,-78.232 ; 96.647,-83.21 ccw(c99.345,-83.21) 97.437,-85.118 98.298,-85.979 ; C11.2@97.155,-78.232 97.155,-82.321 ccw(c99.853,-82.321) 97.945,-84.229 99.159,-85.443 ccw(c101.067,-83.535) 101.067,-86.233 106.68,-86.233 ; 105.791,-86.36 111.277,-86.36 ; 106.68,-86.36 109.753,-86.36 ccw(c109.753,-83.662) 111.661,-85.57 113.256,-83.975 ccw(c111.348,-82.067) 114.046,-82.067 C12.2@114.046,-77.597 ; 108.966,-86.233 110.515,-86.233 ccw(c110.515,-83.535) 112.423,-85.443 113.383,-84.483 ccw(c111.475,-82.575) 114.173,-82.575 C12.2@114.173,-78.486 ; 110.236,-86.36 112.166,-86.36 ccw(c112.166,-83.662) 114.074,-85.57 ccw(c112.303,-83.798) 114.808,-83.798 114.808,-78.539 ccw(c114.374,-78.539) C12.2@114.681,-78.232 ; C12.2@114.053,-78.479 cw(c112.842,-79.69) 114.554,-79.69 ; 114.554,-83.083 C12.2@114.554,-78.232
-18V: 
GND: C1.2 C4.2 C5.1 C7.1 C8.2 C9.2 C10.2 C11.1 C12.1 C13.2 C14.2 P1.1 P2.2 P3.2 Q3.1 Q4.2 Q6.1 R1.2 R5.1 R12.2 R14.2 | length 4777.4
  Bottom Layer w1: 60.833,-15.24 Q4.2@66.824,-15.24 ; 61.632,-19.902 ccw(c61.415,-19.685) 61.722,-19.685 cw(c64.788,-19.685) 61.976,-18.463 cw(c64.788,-19.685) 62.57,-17.569 cw(c64.788,-19.685) 62.62,-17.517 64.77,-15.367 ; 64.225,-12.356 cw(c64.008,-12.139) 64.008,-12.446 ccw(c66.154,-12.446) 64.637,-13.964 65.352,-14.679 ccw(c65.786,-14.246) 65.786,-14.859 ; 66.451,-15.24 ccw(c66.451,-14.373) Q4.2@67.064,-14.986 ; 66.451,-15.24 ccw(c66.451,-14.373) Q4.2@67.064,-14.986 ; 66.451,-15.24 ccw(c66.451,-14.373) Q4.2@67.064,-14.986 ; 66.451,-15.24 ccw(c66.451,-14.373) Q4.2@67.064,-14.986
